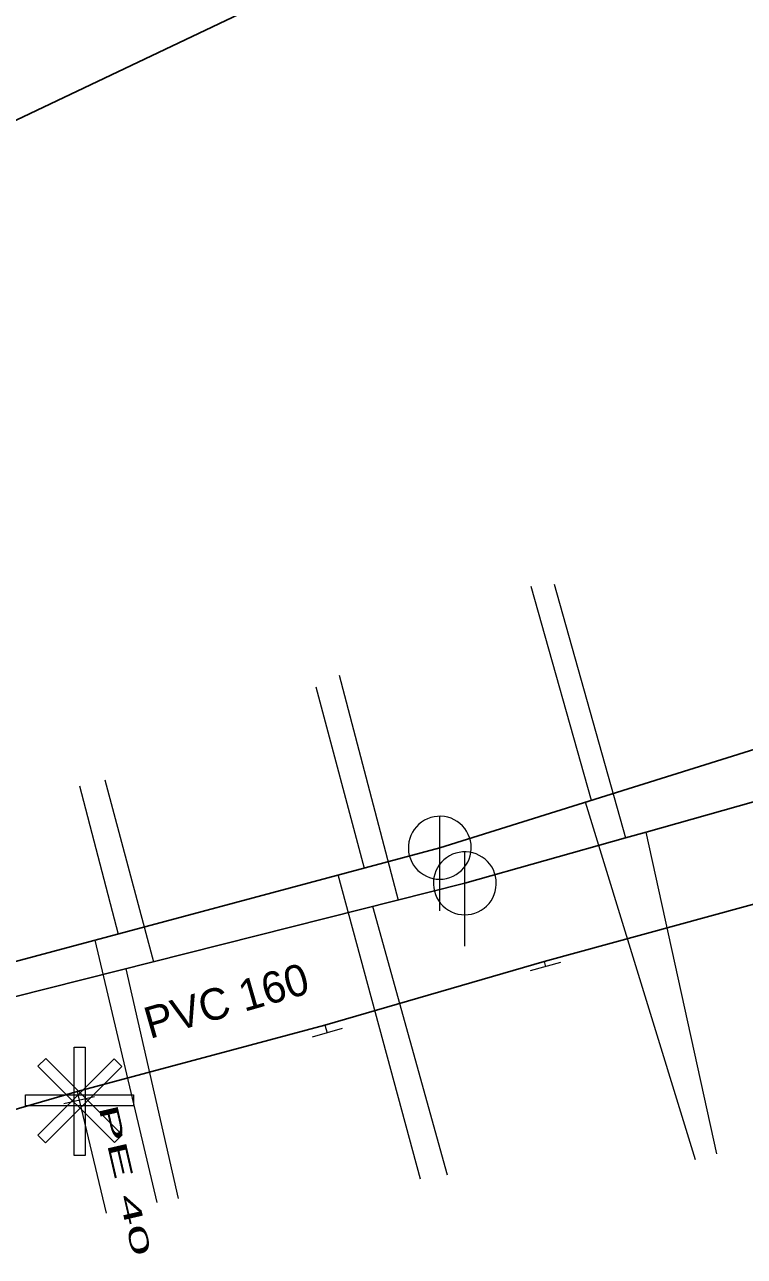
# Model space of a CAD drawing. Extents: x -809028 to -807737, y -990545 to -989489.
# Drawn here: x -808646.26 to -808623.39, y -989740.24 to -989701.11 of the extents above; entities that cross this region are included whole.
import ezdxf

# ---------------------------------------------------------------- set-up
doc = ezdxf.new("R2010")
doc.units = 0
doc.header["$LTSCALE"] = 0.32
for name, color, linetype, lineweight in [('1', 7, 'Continuous', 13), ('11', 7, 'Continuous', 13), ('12', 7, 'Continuous', 13), ('13', 7, 'Continuous', 13), ('14', 7, 'Continuous', 25), ('17', 7, 'Continuous', 25), ('22', 7, 'Continuous', 13), ('34', 7, 'Continuous', 13)]:
    doc.layers.add(name, color=color, linetype=linetype, lineweight=lineweight)

msp = doc.modelspace()

# ---------------------------------------------------------------- linework, layer by layer
at = {"layer": '11'}
for p, q in [((-808630.171, -989718.947), (-808628.253, -989725.75)), ((-808629.432, -989718.885), (-808627.164, -989726.947)), ((-808636.267, -989721.779), (-808634.388, -989728.922)), ((-808637.006, -989722.148), (-808635.476, -989727.902)), ((-808643.717, -989725.104), (-808642.165, -989730.883)), ((-808644.518, -989725.289), (-808643.29, -989729.999)), ((-808624.938, -989737.172), (-808628.439, -989725.808)), ((-808624.26, -989736.987), (-808626.507, -989726.761)), ((-808633.681, -989737.788), (-808636.299, -989728.123)), ((-808632.819, -989737.665), (-808635.199, -989729.127)), ((-808642.055, -989738.527), (-808644.025, -989730.196)), ((-808641.377, -989738.403), (-808643.034, -989731.102))]:
    msp.add_line(p, q, dxfattribs=at)
at = {"layer": '12'}
for points in [[(-808644.688, -989733.595), (-808644.338, -989733.595), (-808644.338, -989737.03), (-808644.688, -989737.03)], [(-808643.422, -989733.959), (-808643.174, -989734.207), (-808645.603, -989736.636), (-808645.85, -989736.388)], [(-808645.841, -989734.198), (-808645.594, -989733.95), (-808643.165, -989736.379), (-808643.412, -989736.627)], [(-808642.804, -989735.104), (-808642.804, -989735.454), (-808646.239, -989735.454), (-808646.239, -989735.104)]]:
    msp.add_lwpolyline(points, close=True, dxfattribs=at)
at = {"layer": '13'}
msp.add_line((-808644.53, -989735.28), (-808643.673, -989738.868), dxfattribs=at)
at = {"layer": '14'}
msp.add_line((-808665.723, -989736.017), (-808633.069, -989727.257), dxfattribs=at)
at = {"layer": '14', "lineweight": 13}
for p, q in [((-808629.754, -989730.875), (-808629.71, -989731.039)), ((-808636.721, -989732.898), (-808636.649, -989733.14)), ((-808644.599, -989735.007), (-808644.53, -989735.28))]:
    msp.add_line(p, q, dxfattribs=at)
at = {"layer": '14'}
for points in [[(-808633.069, -989727.257), (-808620.411, -989723.296), (-808619.305, -989722.982), (-808614.478, -989721.613), (-808613.777, -989721.419), (-808598.899, -989717.298)], [(-808632.272, -989728.388), (-808627.164, -989726.947), (-808626.507, -989726.761), (-808619.273, -989724.719), (-808618.7, -989724.557), (-808613.168, -989722.995), (-808612.517, -989722.811), (-808599.298, -989719.079)], [(-808664.717, -989736.982), (-808656.543, -989734.509), (-808632.272, -989728.388)]]:
    msp.add_lwpolyline(points, dxfattribs=at)
at = {"layer": '17'}
for points in [[(-808462.359, -989745.649), (-808463.609, -989745.59), (-808609.824, -989686.686), (-808669.927, -989715.25), (-808715.085, -989727.543), (-808715.98, -989727.807)], [(-808612.572, -989726.644), (-808622.36, -989728.852), (-808629.754, -989730.875), (-808636.721, -989732.898), (-808644.599, -989735.007), (-808652.064, -989737.158), (-808652.748, -989737.315), (-808654.901, -989737.974)]]:
    msp.add_lwpolyline(points, dxfattribs=at)
at = {"layer": '22'}
for p, q in [((-808633.069, -989729.257), (-808633.068, -989726.257)), ((-808632.272, -989730.388), (-808632.271, -989727.388))]:
    msp.add_line(p, q, dxfattribs=at)
for points in [[(-808632.069, -989727.257), (-808632.074, -989727.148), (-808632.092, -989727.04), (-808632.122, -989726.934), (-808632.162, -989726.833), (-808632.214, -989726.736), (-808632.276, -989726.646), (-808632.348, -989726.563), (-808632.428, -989726.489), (-808632.516, -989726.423), (-808632.61, -989726.368), (-808632.71, -989726.323), (-808632.815, -989726.29), (-808632.922, -989726.268), (-808633.031, -989726.258), (-808633.141, -989726.26), (-808633.249, -989726.274), (-808633.356, -989726.299), (-808633.459, -989726.336), (-808633.557, -989726.385), (-808633.649, -989726.443), (-808633.735, -989726.512), (-808633.812, -989726.589), (-808633.881, -989726.675), (-808633.94, -989726.767), (-808633.988, -989726.865), (-808634.025, -989726.968), (-808634.051, -989727.075), (-808634.065, -989727.183), (-808634.068, -989727.293), (-808634.058, -989727.402), (-808634.037, -989727.509), (-808634.003, -989727.613), (-808633.959, -989727.713), (-808633.904, -989727.808), (-808633.838, -989727.896), (-808633.764, -989727.976), (-808633.681, -989728.048), (-808633.591, -989728.11), (-808633.495, -989728.162), (-808633.393, -989728.203), (-808633.288, -989728.233), (-808633.18, -989728.251), (-808633.07, -989728.257), (-808632.961, -989728.251), (-808632.853, -989728.233), (-808632.748, -989728.204), (-808632.646, -989728.163), (-808632.549, -989728.111), (-808632.459, -989728.049), (-808632.376, -989727.978), (-808632.301, -989727.898), (-808632.236, -989727.81), (-808632.18, -989727.716), (-808632.136, -989727.616), (-808632.102, -989727.512), (-808632.08, -989727.404), (-808632.07, -989727.295)], [(-808631.272, -989728.388), (-808631.277, -989728.279), (-808631.295, -989728.171), (-808631.325, -989728.065), (-808631.365, -989727.964), (-808631.417, -989727.867), (-808631.479, -989727.777), (-808631.551, -989727.694), (-808631.631, -989727.62), (-808631.719, -989727.554), (-808631.813, -989727.499), (-808631.913, -989727.454), (-808632.018, -989727.421), (-808632.125, -989727.399), (-808632.234, -989727.389), (-808632.344, -989727.391), (-808632.452, -989727.405), (-808632.559, -989727.43), (-808632.662, -989727.467), (-808632.76, -989727.516), (-808632.852, -989727.574), (-808632.938, -989727.643), (-808633.015, -989727.72), (-808633.084, -989727.806), (-808633.143, -989727.898), (-808633.191, -989727.996), (-808633.228, -989728.099), (-808633.254, -989728.206), (-808633.268, -989728.314), (-808633.271, -989728.424), (-808633.261, -989728.533), (-808633.24, -989728.64), (-808633.206, -989728.744), (-808633.162, -989728.844), (-808633.107, -989728.939), (-808633.041, -989729.027), (-808632.967, -989729.107), (-808632.884, -989729.179), (-808632.794, -989729.241), (-808632.698, -989729.293), (-808632.596, -989729.334), (-808632.491, -989729.364), (-808632.383, -989729.382), (-808632.273, -989729.388), (-808632.164, -989729.382), (-808632.056, -989729.364), (-808631.951, -989729.335), (-808631.849, -989729.294), (-808631.752, -989729.242), (-808631.662, -989729.18), (-808631.579, -989729.109), (-808631.504, -989729.029), (-808631.439, -989728.941), (-808631.383, -989728.847), (-808631.339, -989728.747), (-808631.305, -989728.643), (-808631.283, -989728.535), (-808631.273, -989728.426)]]:
    msp.add_lwpolyline(points, close=True, dxfattribs=at)
at = {"layer": '34'}
for p, q in [((-808629.227, -989730.908), (-808630.192, -989731.168)), ((-808636.169, -989732.998), (-808637.128, -989733.28)), ((-808644.042, -989735.167), (-808645.017, -989735.391))]:
    msp.add_line(p, q, dxfattribs=at)

# ---------------------------------------------------------------- texts
at = {"layer": '1'}
msp.add_text('PVC 160 ', height=1, rotation=16, dxfattribs=at).set_placement((-808642.287, -989733.335))
at = {"layer": '1', "width": 2.25}
msp.add_text('PE 40 ', height=0.6, rotation=283, dxfattribs=at).set_placement((-808643.923, -989735.488))

doc.saveas('drawing.dxf')
